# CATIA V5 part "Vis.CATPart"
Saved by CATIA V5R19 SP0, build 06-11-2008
Part number: Vis
Publications: "rvis", "Lvis", "r"
Bounding box of the stored display mesh (mm): x -200 to 20, y -7 to 7, z -6.824 to 6.824
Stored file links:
  G:\EU_thinkMotion\CFAO_2010\MMS_groupe3\MMS_groupe3\A reprendre\evulliez\evulliez\Vis.CATPart
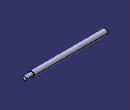
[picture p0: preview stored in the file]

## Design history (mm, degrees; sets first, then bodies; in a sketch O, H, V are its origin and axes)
Parameters
  rvis = 7 mm
  Lvis = 200 mm
  r = 5 mm
Body1 (main body)
  Sketch1 on yz-plane, origin (0, 0, 0), H (0, 1, 0), V (0, 0, 1)
    circle A1 centre (0, 0) radius 7
    radius A1 = 7 {= rvis}
  Pad1: profile Sketch1, direction (-1, 0, 0), length 200 {= Lvis}
  Sketch2 on start face of Pad1, origin (0, 0, 0), H (0, 1, 0), V (0, 0, 1)
    circle A1 centre (0, 0) radius 5
    radius A1 = 5 {= r}
  Pad2: profile Sketch2, direction (1, 0, 0), length 20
